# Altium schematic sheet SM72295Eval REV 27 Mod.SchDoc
size D; DrawnBy: *Dee Lim; Engineer: *Steve Brown; DocumentNumber: *TIDA-00558; PageSetup: Record=PageOptions¦CenterHorizontal=True¦CenterVertical=True¦PrintScale=0.51¦XCorrection=1.00¦YCorrection=1.00¦PrintKind=1¦BorderSize=5000000¦LeftOffset=0¦BottomOffset=0¦Orientation=2¦PaperLength=1000¦PaperWidth=1000¦Scale=100¦PaperSource=15¦PrintQuality=600¦MediaType=1¦DitherType=10¦PaperKind=Tabloid (11 x 17")¦PrintScaleMode=1
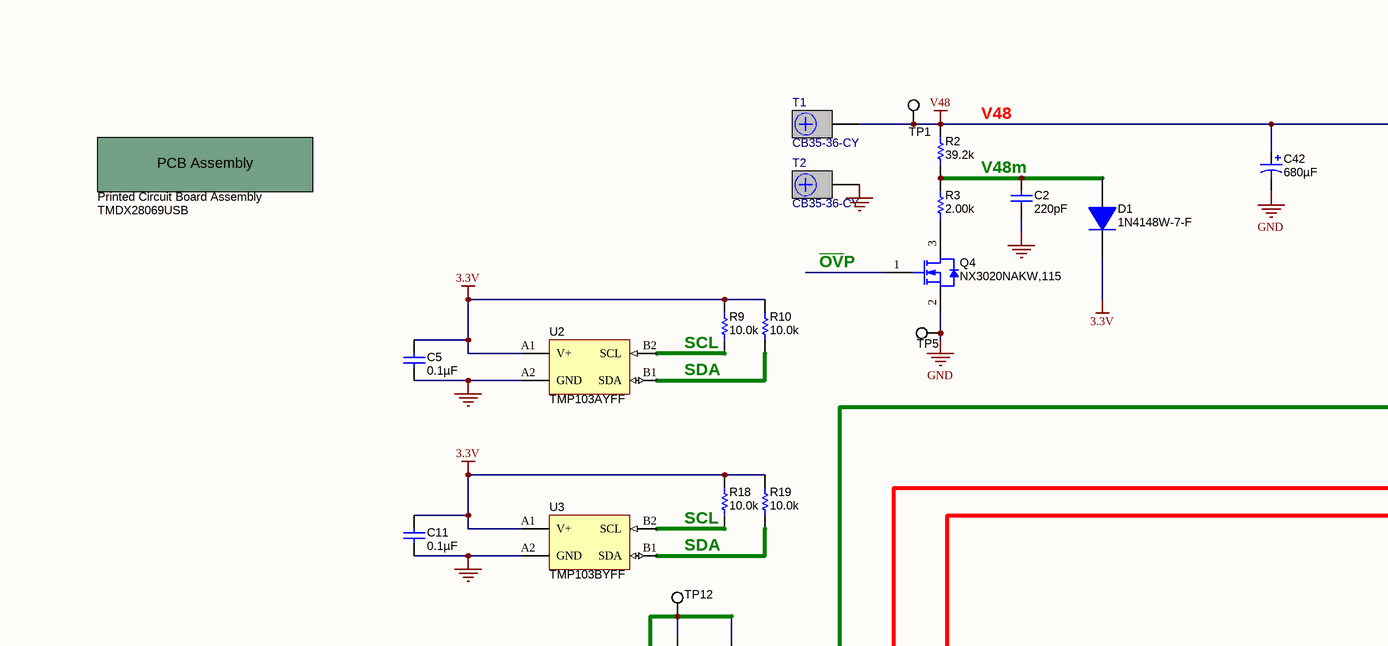
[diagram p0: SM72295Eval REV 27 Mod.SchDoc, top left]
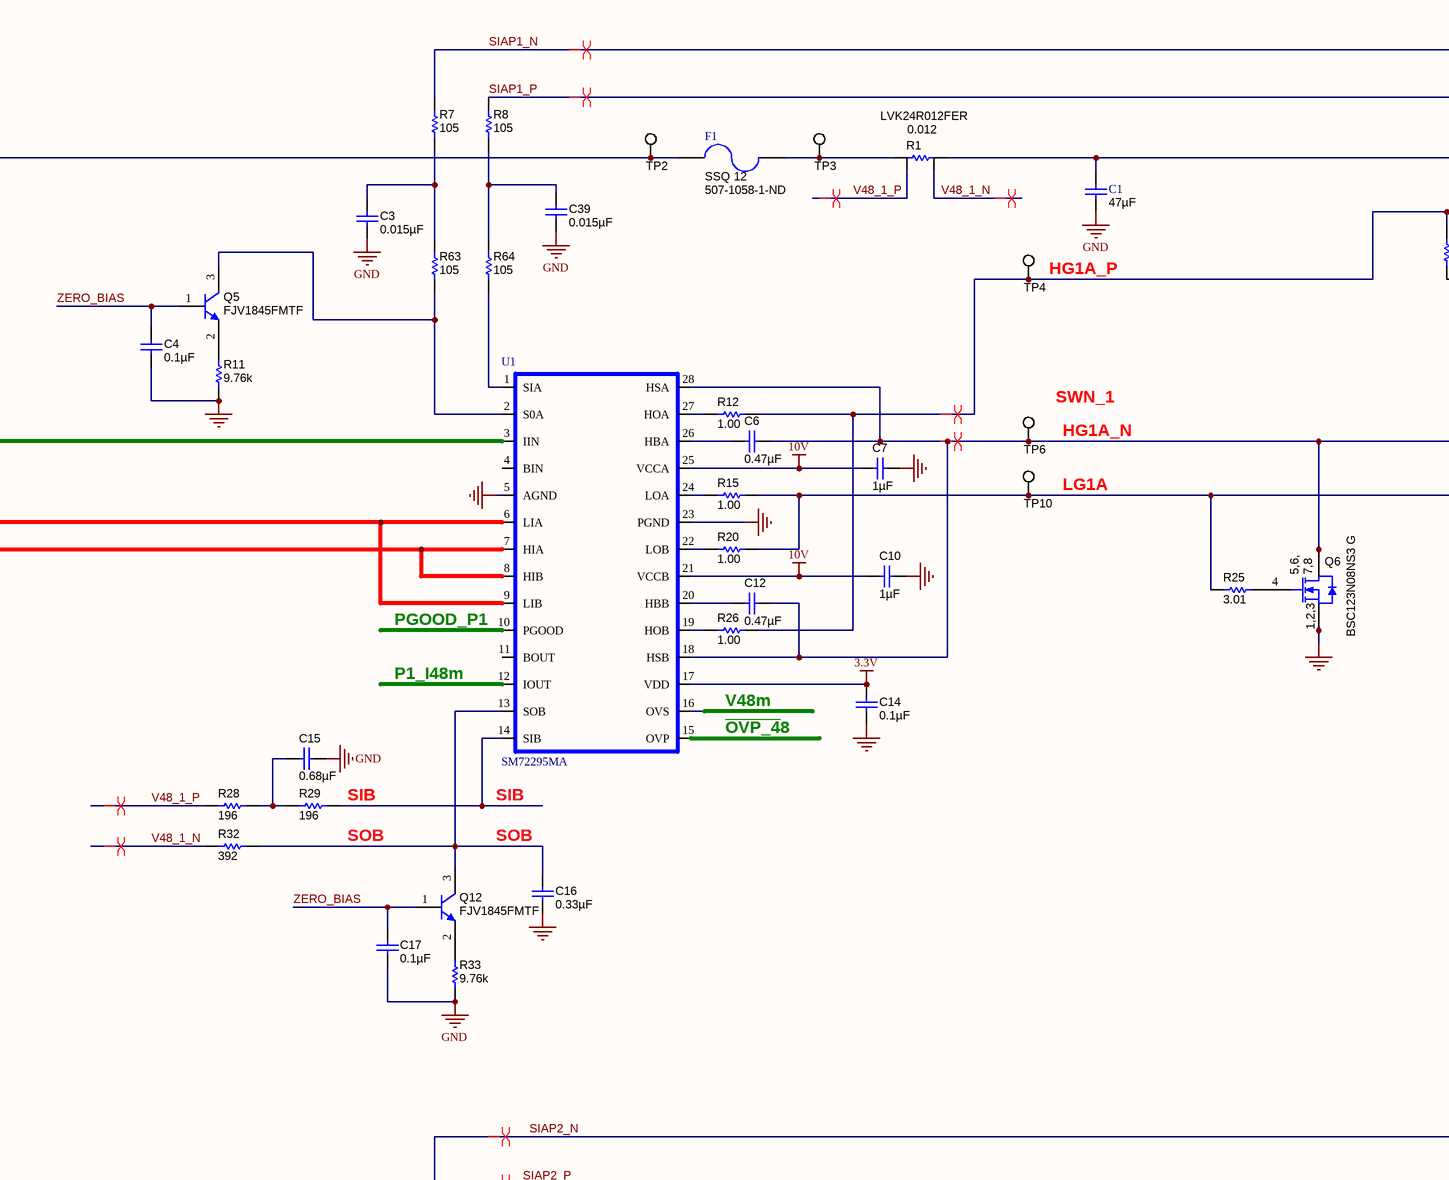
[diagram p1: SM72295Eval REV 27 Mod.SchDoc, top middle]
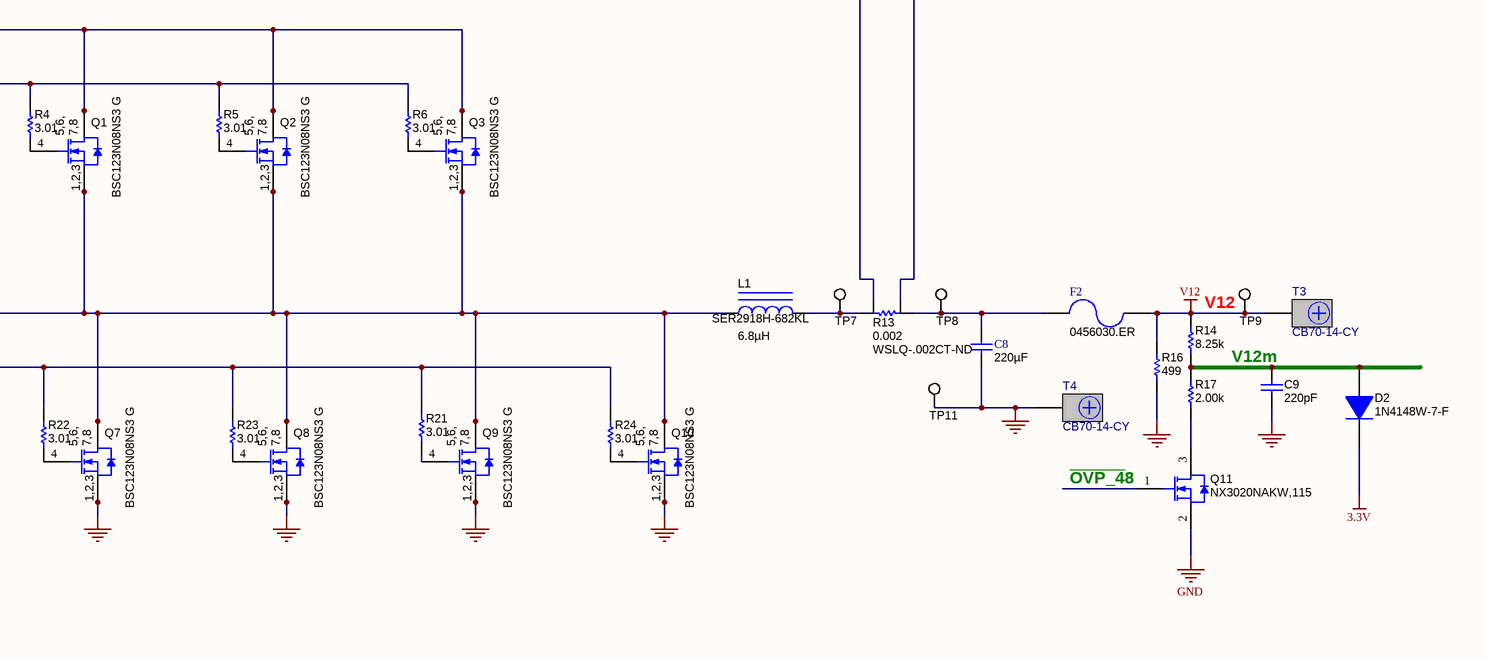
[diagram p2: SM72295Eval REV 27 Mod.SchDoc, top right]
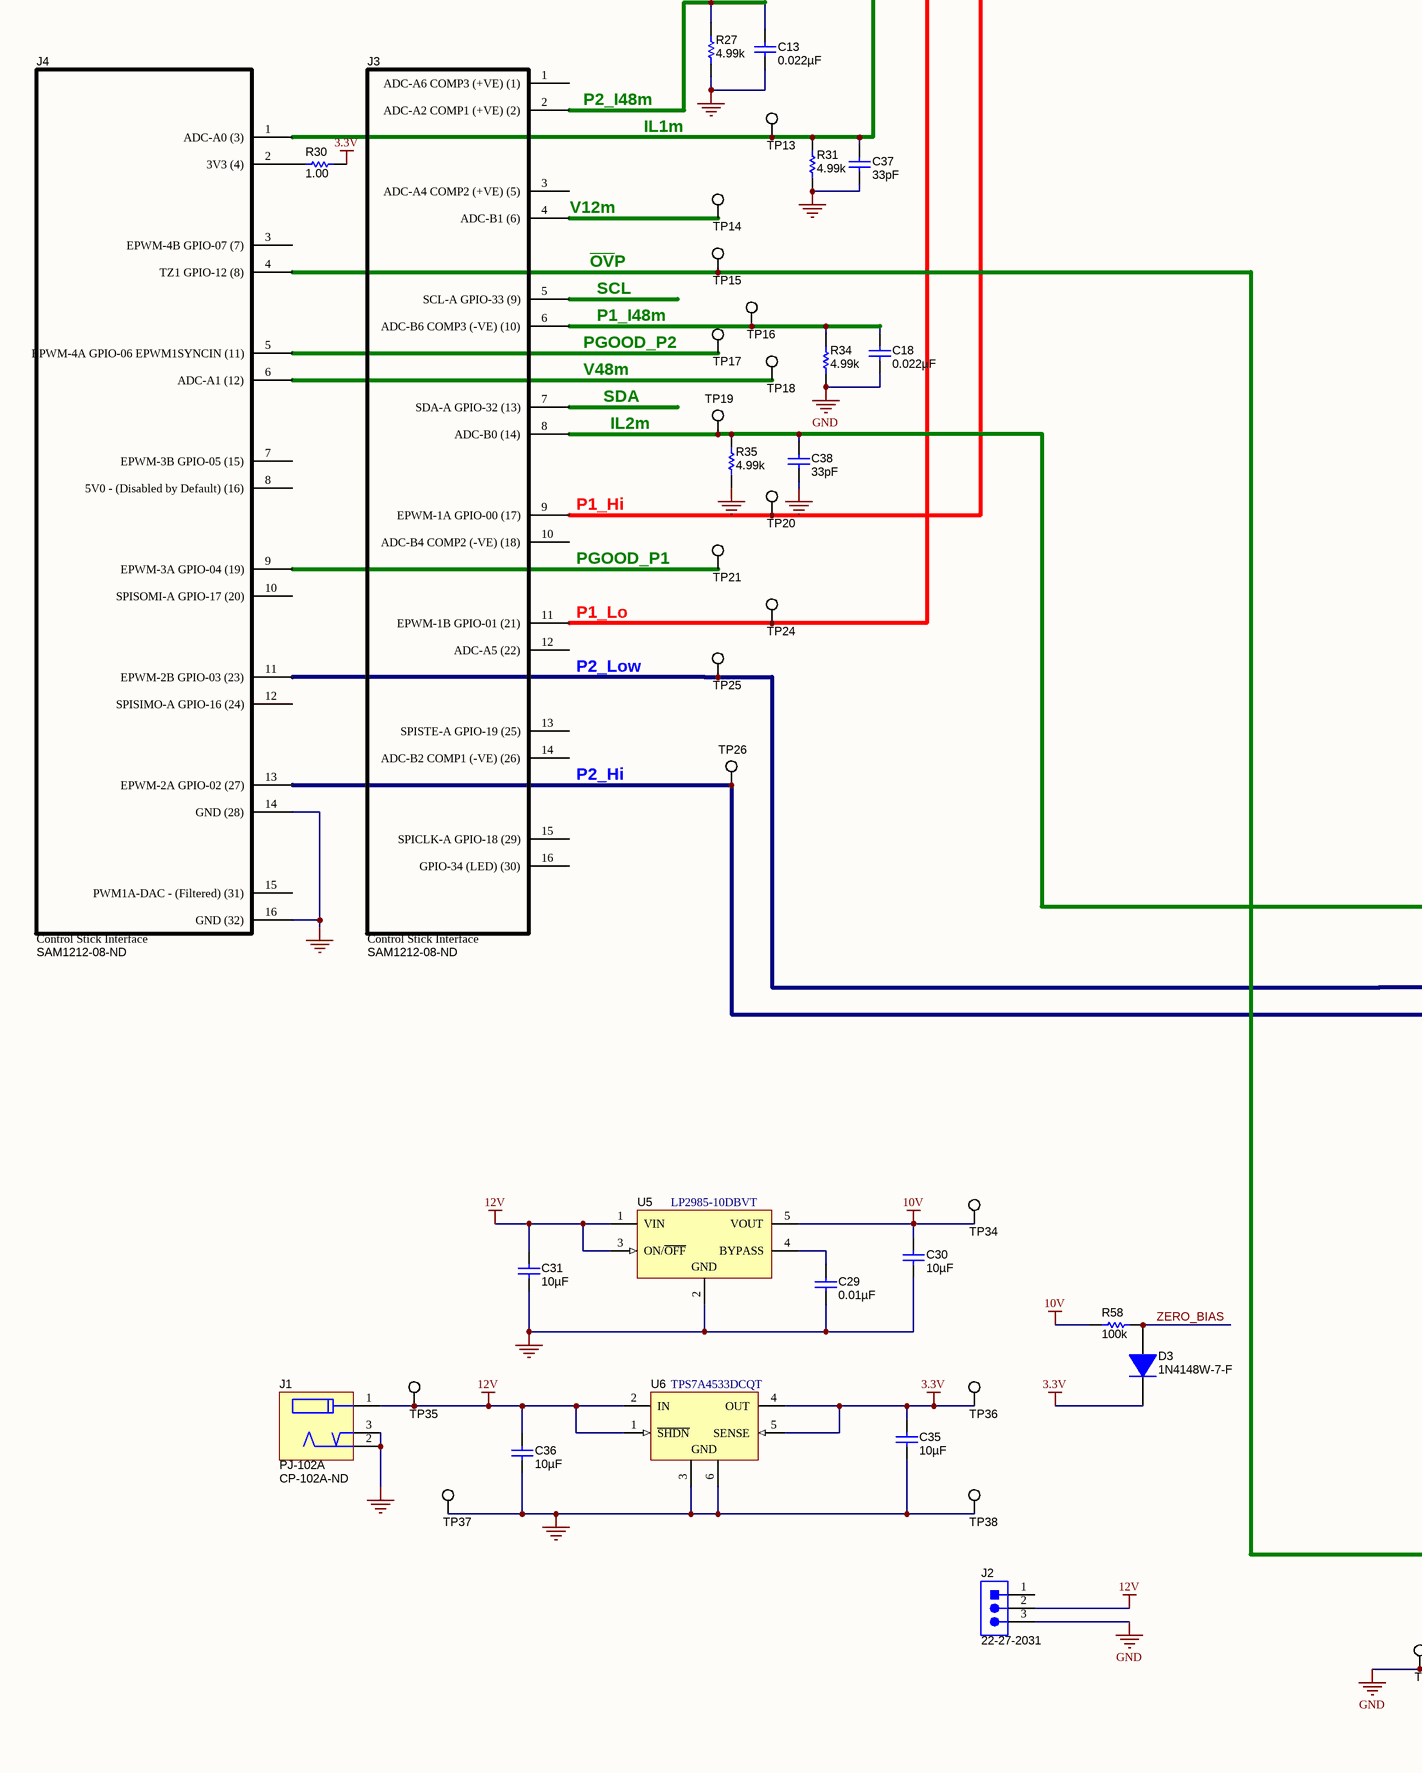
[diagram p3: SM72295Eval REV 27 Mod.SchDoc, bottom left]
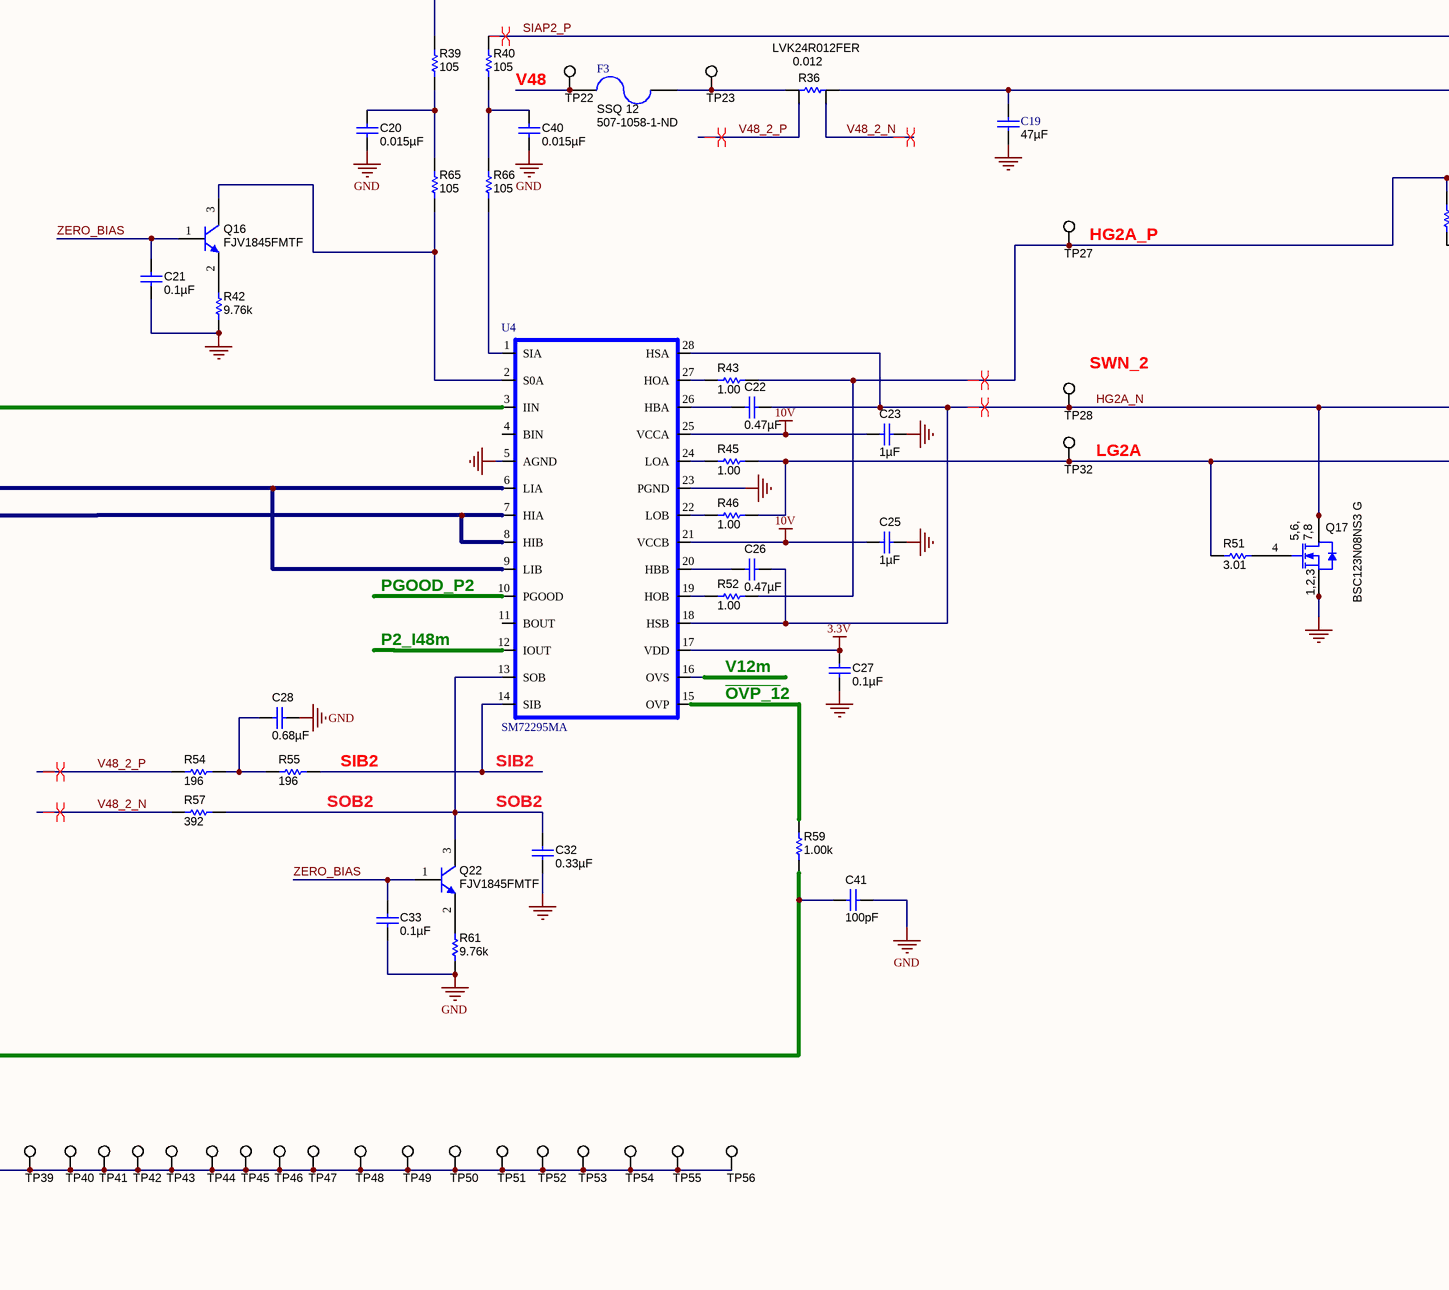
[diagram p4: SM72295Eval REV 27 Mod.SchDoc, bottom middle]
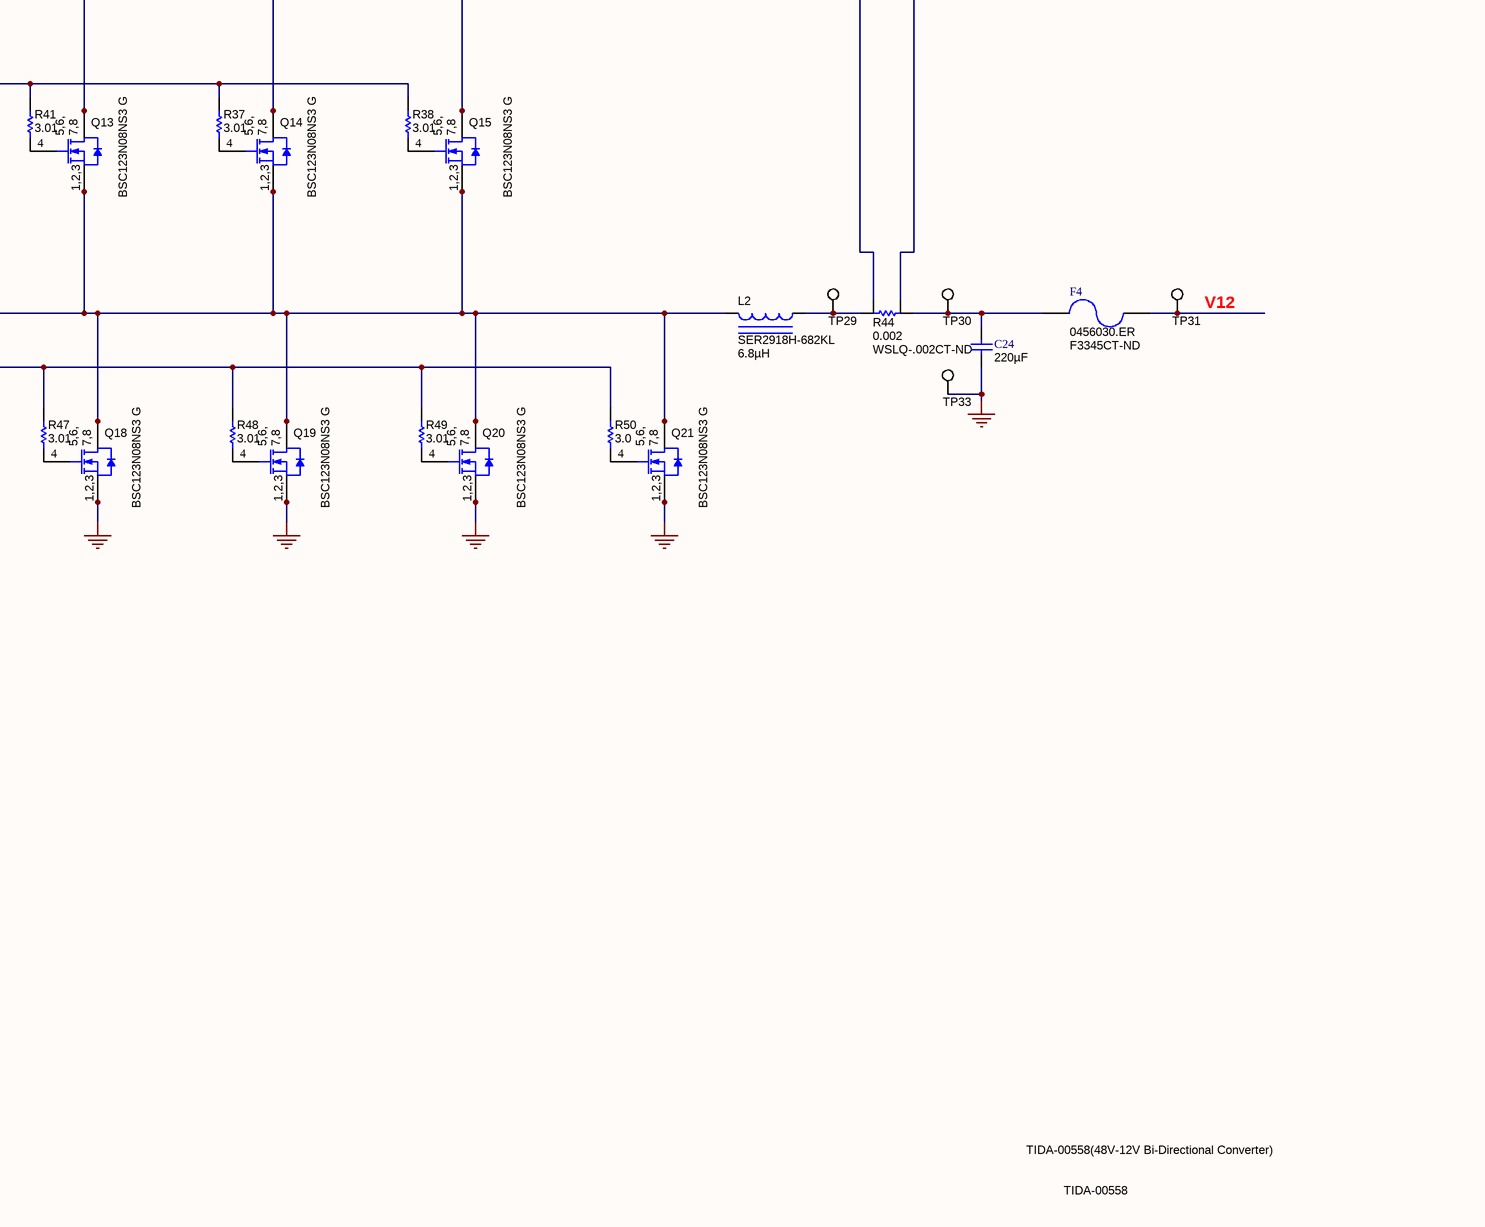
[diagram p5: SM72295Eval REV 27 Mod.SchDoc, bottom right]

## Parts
C1  ValueDisplayed: 47µF  [AVX-ST20-J10]  (hidden comment: RT201C476MAJ10)
C2  ValueDisplayed: 220pF  [0805_HV]  (hidden comment: C0805C221J1GACTU)
C3  ValueDisplayed: 0.015µF  [1206]  (hidden comment: 12061C153JAT2A)
C4  ValueDisplayed: 0.1µF  [0805_HV]  (hidden comment: 08055C104KAT2A)
C5  ValueDisplayed: 0.1µF  [0805_HV]  (hidden comment: 08053C104KAT2A)
C6  ValueDisplayed: 0.47µF  [0805_HV]  (hidden comment: C2012X7R1E474K)
C7  ValueDisplayed: 1µF  [0805_HV]  (hidden comment: C2012X7R1E105K)
C8  ValueDisplayed: 220µF  [AVX-ST20-J10]  (hidden comment: RT203C227MAJ10)
C9  ValueDisplayed: 220pF  [0805_HV]  (hidden comment: 08055A221JAT2A)
C10  ValueDisplayed: 1µF  [0805_HV]  (hidden comment: C2012X7R1E105K)
C11  ValueDisplayed: 0.1µF  [0805_HV]  (hidden comment: 08053C104KAT2A)
C12  ValueDisplayed: 0.47µF  [0805_HV]  (hidden comment: C2012X7R1E474K)
C13  ValueDisplayed: 0.022µF  [0805_HV]  (hidden comment: C0805C223K5RACTU)
C14  ValueDisplayed: 0.1µF  [0805_HV]  (hidden comment: 08053C104KAT2A)
C15  ValueDisplayed: 0.68µF  [1206_190]  (hidden comment: CGA5L2X7R2A684K160AA)
C16  ValueDisplayed: 0.33µF  [1206]  (hidden comment: C3216X7R2A334K130AA)
C17  ValueDisplayed: 0.1µF  [0805_HV]  (hidden comment: 08055C104KAT2A)
C18  ValueDisplayed: 0.022µF  [0805_HV]  (hidden comment: C0805C223K5RACTU)
C19  ValueDisplayed: 47µF  [AVX-ST20-J10]  (hidden comment: RT201C476MAJ10)
C20  ValueDisplayed: 0.015µF  [1206]  (hidden comment: 12061C153JAT2A)
C21  ValueDisplayed: 0.1µF  [0805_HV]  (hidden comment: 08055C104KAT2A)
C22  ValueDisplayed: 0.47µF  [0805_HV]  (hidden comment: C2012X7R1E474K)
C23  ValueDisplayed: 1µF  [0805_HV]  (hidden comment: C2012X7R1E105K)
C24  ValueDisplayed: 220µF  [AVX-ST20-J10]  (hidden comment: RT203C227MAJ10)
C25  ValueDisplayed: 1µF  [0805_HV]  (hidden comment: C2012X7R1E105K)
C26  ValueDisplayed: 0.47µF  [0805_HV]  (hidden comment: C2012X7R1E474K)
C27  ValueDisplayed: 0.1µF  [0805_HV]  (hidden comment: 08053C104KAT2A)
C28  ValueDisplayed: 0.68µF  [1206_190]  (hidden comment: CGA5L2X7R2A684K160AA)
C29  ValueDisplayed: 0.01µF  [0805_HV]  (hidden comment: 08055C103JAT2A)
C30  ValueDisplayed: 10µF  [1206]  (hidden comment: GRM31CR71E106KA12L)
C31  ValueDisplayed: 10µF  [1206]  (hidden comment: GRM31CR71E106KA12L)
C32  ValueDisplayed: 0.33µF  [1206]  (hidden comment: C3216X7R2A334K130AA)
C33  ValueDisplayed: 0.1µF  [0805_HV]  (hidden comment: 08055C104KAT2A)
C35  ValueDisplayed: 10µF  [0805_145]  (hidden comment: EMK212BB7106MG-T)
C36  ValueDisplayed: 10µF  [1206]  (hidden comment: GRM31CR71E106KA12L)
C37  ValueDisplayed: 33pF  [0805_HV]  (hidden comment: 08055A330JAT2A)
C38  ValueDisplayed: 33pF  [0805_HV]  (hidden comment: 08055A330JAT2A)
C39  ValueDisplayed: 0.015µF  [1206]  (hidden comment: 12061C153JAT2A)
C40  ValueDisplayed: 0.015µF  [1206]  (hidden comment: 12061C153JAT2A)
C41  ValueDisplayed: 100pF  [0805_HV]  (hidden comment: 08055A101JAT2A)
C42  ValueDisplayed: 680µF  [GPA_1800x3000]  (hidden comment: EGPA800ELL681MM30S)
D1  1N4148W-7-F  [SOD-123]
D2  1N4148W-7-F  [SOD-123]
D3  1N4148W-7-F  [SOD-123]
F1  SSQ 12  Supplier Part Number: 507-1058-1-ND  [SSQ]
F2  0456030.ER  [456]
F3  SSQ 12  Supplier Part Number: 507-1058-1-ND  [SSQ]
F4  0456030.ER  Supplier Part Number: F3345CT-ND  [456]
J1  PJ-102A  Supplier Part Number: CP-102A-ND  [PJ-102A]
J2  22-27-2031  [MOLEX_22-27-2031]
J3  Name: Control Stick Interface  Supplier Part Number: SAM1212-08-ND  [Samtec_SSW-108-01-x-D]  (hidden comment: TMDX28069USB_HALF ONE)
J4  Name: Control Stick Interface  Supplier Part Number: SAM1212-08-ND  [Samtec_SSW-108-01-x-D]  (hidden comment: TMDX28069USB_HALF TWO)
L1  SER2918H-682KL  ValueDisplayed: 6.8µH  [SER2918]
L2  SER2918H-682KL  ValueDisplayed: 6.8µH  [SER2918]
PCBA1  Printed Circuit Board Assembly  (mechanical)
Q1  BSC123N08NS3 G  [PG-TDSON-8 WITH VIAS]
Q2  BSC123N08NS3 G  [PG-TDSON-8 WITH VIAS]
Q3  BSC123N08NS3 G  [PG-TDSON-8 WITH VIAS]
Q4  NX3020NAKW,115  [SOT-323]
Q5  FJV1845FMTF  [SOT-23]
Q6  BSC123N08NS3 G  [PG-TDSON-8 WITH VIAS]
Q7  BSC123N08NS3 G  [PG-TDSON-8 WITH VIAS]
Q8  BSC123N08NS3 G  [PG-TDSON-8 WITH VIAS]
Q9  BSC123N08NS3 G  [PG-TDSON-8 WITH VIAS]
Q10  BSC123N08NS3 G  [PG-TDSON-8 WITH VIAS]
Q11  NX3020NAKW,115  [SOT-323]
Q12  FJV1845FMTF  [SOT-23]
Q13  BSC123N08NS3 G  [PG-TDSON-8 WITH VIAS]
Q14  BSC123N08NS3 G  [PG-TDSON-8 WITH VIAS]
Q15  BSC123N08NS3 G  [PG-TDSON-8 WITH VIAS]
Q16  FJV1845FMTF  [SOT-23]
Q17  BSC123N08NS3 G  [PG-TDSON-8 WITH VIAS]
Q18  BSC123N08NS3 G  [PG-TDSON-8 WITH VIAS]
Q19  BSC123N08NS3 G  [PG-TDSON-8 WITH VIAS]
Q20  BSC123N08NS3 G  [PG-TDSON-8 WITH VIAS]
Q21  BSC123N08NS3 G  [PG-TDSON-8 WITH VIAS]
Q22  FJV1845FMTF  [SOT-23]
R1  LVK24R012FER  ValueDisplayed: 0.012  [LVK24]
R2  ValueDisplayed: 39.2k  [0805_HV]  (hidden comment: CRCW080539K2FKEA)
R3  ValueDisplayed: 2.00k  [0805_HV]  (hidden comment: CRCW08052K00FKEA)
R4  ValueDisplayed: 3.01  [0805_HV]  (hidden comment: CRCW08053R01FKEA)
R5  ValueDisplayed: 3.01  [0805_HV]  (hidden comment: CRCW08053R01FKEA)
R6  ValueDisplayed: 3.01  [0805_HV]  (hidden comment: CRCW08053R01FKEA)
R7  ValueDisplayed: 105  [0805_HV]  (hidden comment: CRCW0805105RFKEA)
R8  ValueDisplayed: 105  [0805_HV]  (hidden comment: CRCW0805105RFKEA)
R9  ValueDisplayed: 10.0k  [0805_HV]  (hidden comment: CRCW080510K0FKEA)
R10  ValueDisplayed: 10.0k  [0805_HV]  (hidden comment: CRCW080510K0FKEA)
R11  ValueDisplayed: 9.76k  [0805_HV]  (hidden comment: CRCW08059K76FKEA)
R12  ValueDisplayed: 1.00  [0805_HV]  (hidden comment: CRCW08051R00FKEA)
R13  ValueDisplayed: 0.002  Supplier Part Number: WSLQ-.002CT-ND  [RES_WSL2726 WITH VIAS]  (hidden comment: WSL27262L000FEB)
R14  ValueDisplayed: 8.25k  [0805_HV]  (hidden comment: CRCW08058K25FKEA)
R15  ValueDisplayed: 1.00  [0805_HV]  (hidden comment: CRCW08051R00FKEA)
R16  ValueDisplayed: 499  [1206]  (hidden comment: CRCW1206499RFKEA)
R17  ValueDisplayed: 2.00k  [0805_HV]  (hidden comment: CRCW08052K00FKEA)
R18  ValueDisplayed: 10.0k  [0805_HV]  (hidden comment: CRCW080510K0FKEA)
R19  ValueDisplayed: 10.0k  [0805_HV]  (hidden comment: CRCW080510K0FKEA)
R20  ValueDisplayed: 1.00  [0805_HV]  (hidden comment: CRCW08051R00FKEA)
R21  ValueDisplayed: 3.01  [0805_HV]  (hidden comment: CRCW08053R01FKEA)
R22  ValueDisplayed: 3.01  [0805_HV]  (hidden comment: CRCW08053R01FKEA)
R23  ValueDisplayed: 3.01  [0805_HV]  (hidden comment: CRCW08053R01FKEA)
R24  ValueDisplayed: 3.01  [0805_HV]  (hidden comment: CRCW08053R01FKEA)
R25  ValueDisplayed: 3.01  [0805_HV]  (hidden comment: CRCW08053R01FKEA)
R26  ValueDisplayed: 1.00  [0805_HV]  (hidden comment: CRCW08051R00FKEA)
R27  ValueDisplayed: 4.99k  [0805_HV]  (hidden comment: CRCW08054K99FKEA)
R28  ValueDisplayed: 196  [0805_HV]  (hidden comment: CRCW0805196RFKEA)
R29  ValueDisplayed: 196  [0805_HV]  (hidden comment: CRCW0805196RFKEA)
R30  ValueDisplayed: 1.00  [0805_HV]  (hidden comment: CRCW08051R00FKEA)
R31  ValueDisplayed: 4.99k  [0805_HV]  (hidden comment: CRCW08054K99FKEA)
R32  ValueDisplayed: 392  [0805_HV]  (hidden comment: CRCW0805392RFKEA)
R33  ValueDisplayed: 9.76k  [0805_HV]  (hidden comment: CRCW08059K76FKEA)
R34  ValueDisplayed: 4.99k  [0805_HV]  (hidden comment: CRCW08054K99FKEA)
R35  ValueDisplayed: 4.99k  [0805_HV]  (hidden comment: CRCW08054K99FKEA)
R36  LVK24R012FER  ValueDisplayed: 0.012  [LVK24]
R37  ValueDisplayed: 3.01  [0805_HV]  (hidden comment: CRCW08053R01FKEA)
R38  ValueDisplayed: 3.01  [0805_HV]  (hidden comment: CRCW08053R01FKEA)
R39  ValueDisplayed: 105  [0805_HV]  (hidden comment: CRCW0805105RFKEA)
R40  ValueDisplayed: 105  [0805_HV]  (hidden comment: CRCW0805105RFKEA)
R41  ValueDisplayed: 3.01  [0805_HV]  (hidden comment: CRCW08053R01FKEA)
R42  ValueDisplayed: 9.76k  [0805_HV]  (hidden comment: CRCW08059K76FKEA)
R43  ValueDisplayed: 1.00  [0805_HV]  (hidden comment: CRCW08051R00FKEA)
R44  ValueDisplayed: 0.002  Supplier Part Number: WSLQ-.002CT-ND  [RES_WSL2726 WITH VIAS]  (hidden comment: WSL27262L000FEB)
R45  ValueDisplayed: 1.00  [0805_HV]  (hidden comment: CRCW08051R00FKEA)
R46  ValueDisplayed: 1.00  [0805_HV]  (hidden comment: CRCW08051R00FKEA)
R47  ValueDisplayed: 3.01  [0805_HV]  (hidden comment: CRCW08053R01FKEA)
R48  ValueDisplayed: 3.01  [0805_HV]  (hidden comment: CRCW08053R01FKEA)
R49  ValueDisplayed: 3.01  [0805_HV]  (hidden comment: CRCW08053R01FKEA)
R50  ValueDisplayed: 3.0  [0805_HV]  (hidden comment: CRCW08053R00JNEA)
R51  ValueDisplayed: 3.01  [0805_HV]  (hidden comment: CRCW08053R01FKEA)
R52  ValueDisplayed: 1.00  [0805_HV]  (hidden comment: CRCW08051R00FKEA)
R54  ValueDisplayed: 196  [0805_HV]  (hidden comment: CRCW0805196RFKEA)
R55  ValueDisplayed: 196  [0805_HV]  (hidden comment: CRCW0805196RFKEA)
R57  ValueDisplayed: 392  [0805_HV]  (hidden comment: CRCW0805392RFKEA)
R58  ValueDisplayed: 100k  [0805_HV]  (hidden comment: CRCW0805100KFKEA)
R59  ValueDisplayed: 1.00k  [0805_HV]  (hidden comment: CRCW08051K00FKEA)
R61  ValueDisplayed: 9.76k  [0805_HV]  (hidden comment: CRCW08059K76FKEA)
R63  ValueDisplayed: 105  [0805_HV]  (hidden comment: CRCW0805105RFKEA)
R64  ValueDisplayed: 105  [0805_HV]  (hidden comment: CRCW0805105RFKEA)
R65  ValueDisplayed: 105  [0805_HV]  (hidden comment: CRCW0805105RFKEA)
R66  ValueDisplayed: 105  [0805_HV]  (hidden comment: CRCW0805105RFKEA)
T1  CB35-36-CY  [CB35-36-CY]
T2  CB35-36-CY  [CB35-36-CY]
T3  CB70-14-CY  [CB70-14-CY]
T4  CB70-14-CY  [CB70-14-CY]
TP1  5015  [Testpoint_Keystone_Miniature]  (value not drawn)
TP2  5015  [Testpoint_Keystone_Miniature]  (value not drawn)
TP3  5015  [Testpoint_Keystone_Miniature]  (value not drawn)
TP4  5015  [Testpoint_Keystone_Miniature]  (value not drawn)
TP5  5015  [Testpoint_Keystone_Miniature]  (value not drawn)
TP6  5015  [Testpoint_Keystone_Miniature]  (value not drawn)
TP7  5015  [Testpoint_Keystone_Miniature]  (value not drawn)
TP8  5015  [Testpoint_Keystone_Miniature]  (value not drawn)
TP9  5015  [Testpoint_Keystone_Miniature]  (value not drawn)
TP10  5015  [Testpoint_Keystone_Miniature]  (value not drawn)
TP11  5015  [Testpoint_Keystone_Miniature]  (value not drawn)
TP12  5015  [Testpoint_Keystone_Miniature]  (value not drawn)
TP13  5015  [Testpoint_Keystone_Miniature]  (value not drawn)
TP14  5015  [Testpoint_Keystone_Miniature]  (value not drawn)
TP15  5015  [Testpoint_Keystone_Miniature]  (value not drawn)
TP16  5015  [Testpoint_Keystone_Miniature]  (value not drawn)
TP17  5015  [Testpoint_Keystone_Miniature]  (value not drawn)
TP18  5015  [Testpoint_Keystone_Miniature]  (value not drawn)
TP19  5015  [Testpoint_Keystone_Miniature]  (value not drawn)
TP20  5015  [Testpoint_Keystone_Miniature]  (value not drawn)
TP21  5015  [Testpoint_Keystone_Miniature]  (value not drawn)
TP22  5015  [Testpoint_Keystone_Miniature]  (value not drawn)
TP23  5015  [Testpoint_Keystone_Miniature]  (value not drawn)
TP24  5015  [Testpoint_Keystone_Miniature]  (value not drawn)
TP25  5015  [Testpoint_Keystone_Miniature]  (value not drawn)
TP26  5015  [Testpoint_Keystone_Miniature]  (value not drawn)
TP27  5015  [Testpoint_Keystone_Miniature]  (value not drawn)
TP28  5015  [Testpoint_Keystone_Miniature]  (value not drawn)
TP29  5015  [Testpoint_Keystone_Miniature]  (value not drawn)
TP30  5015  [Testpoint_Keystone_Miniature]  (value not drawn)
TP31  5015  [Testpoint_Keystone_Miniature]  (value not drawn)
TP32  5015  [Testpoint_Keystone_Miniature]  (value not drawn)
TP33  5015  [Testpoint_Keystone_Miniature]  (value not drawn)
TP34  5015  [Testpoint_Keystone_Miniature]  (value not drawn)
TP35  5015  [Testpoint_Keystone_Miniature]  (value not drawn)
TP36  5015  [Testpoint_Keystone_Miniature]  (value not drawn)
TP37  5015  [Testpoint_Keystone_Miniature]  (value not drawn)
TP38  5015  [Testpoint_Keystone_Miniature]  (value not drawn)
TP39  5015  [Testpoint_Keystone_Miniature]  (value not drawn)
TP40  5015  [Testpoint_Keystone_Miniature]  (value not drawn)
TP41  5015  [Testpoint_Keystone_Miniature]  (value not drawn)
TP42  5015  [Testpoint_Keystone_Miniature]  (value not drawn)
TP43  5015  [Testpoint_Keystone_Miniature]  (value not drawn)
TP44  5015  [Testpoint_Keystone_Miniature]  (value not drawn)
TP45  5015  [Testpoint_Keystone_Miniature]  (value not drawn)
TP46  5015  [Testpoint_Keystone_Miniature]  (value not drawn)
TP47  5015  [Testpoint_Keystone_Miniature]  (value not drawn)
TP48  5015  [Testpoint_Keystone_Miniature]  (value not drawn)
TP49  5015  [Testpoint_Keystone_Miniature]  (value not drawn)
TP50  5015  [Testpoint_Keystone_Miniature]  (value not drawn)
TP51  5015  [Testpoint_Keystone_Miniature]  (value not drawn)
TP52  5015  [Testpoint_Keystone_Miniature]  (value not drawn)
TP53  5015  [Testpoint_Keystone_Miniature]  (value not drawn)
TP54  5015  [Testpoint_Keystone_Miniature]  (value not drawn)
TP55  5015  [Testpoint_Keystone_Miniature]  (value not drawn)
TP56  5015  [Testpoint_Keystone_Miniature]  (value not drawn)
U1  SM72295MA  [SO28_DW]
U2  TMP103AYFF  [YFF0004AAAA]
U3  TMP103BYFF  [YFF0004AAAA]
U4  SM72295MA  [SO28_DW]
U5  LP2985-10DBVT  [DBV0005A_N]
U6  TPS7A4533DCQT  [DCQ0006A_N]

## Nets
3.3V: C5.1 C11.1 C14.1 C27.1 C35.1 D1.1(K) D2.1(K) D3.1(K) R9.1 R10.1 R18.1 R19.1 R30.2 TP36.1 U1.17(VDD) U2.A1(V+) U3.A1(V+) U4.17(VDD) U6.4(OUT) U6.5(SENSE)
10V: C7.1 C10.1 C23.1 C25.1 C30.1 R58.1 TP34.1 U1.21(VCCB) U1.25(VCCA) U4.21(VCCB) U4.25(VCCA) U5.5(VOUT)
12V: C31.1 C36.1 J1.1 J2.2 TP35.1 U5.1(VIN) U5.3(ON/~{OFF}) U6.1(~{SHDN}) U6.2(IN)
GND: C1.1 C2.2 C3.1 C4.2 C5.2 C7.2 C8.1 C9.2 C10.2 C11.2 C13.2 C14.2 C15.2 C16.2 C17.2 C18.2 C19.1 C20.1 C21.2 C23.2 C24.1 C25.2 C27.2 C28.2 C29.2 C30.2 C31.2 C32.2 C33.2 C35.2 C36.2 C37.2 C38.2 C39.1 C40.1 C41.1 C42.2(-) J1.2 J1.3 J2.3 J4.14(GND_(28)) J4.16(GND_(32)) Q4.2(S) Q6.1(S) Q6.2(S) Q6.3(S) Q7.1(S) Q7.2(S) Q7.3(S) Q8.1(S) Q8.2(S) Q8.3(S) Q9.1(S) Q9.2(S) Q9.3(S) Q10.1(S) Q10.2(S) Q10.3(S) Q11.2(S) Q17.1(S) Q17.2(S) Q17.3(S) Q18.1(S) Q18.2(S) Q18.3(S) Q19.1(S) Q19.2(S) Q19.3(S) Q20.1(S) Q20.2(S) Q20.3(S) Q21.1(S) Q21.2(S) Q21.3(S) R11.1 R16.1 R27.1 R31.1 R33.1 R34.1 R35.1 R42.1 R61.1 T2.1 T4.1 TP5.1 TP11.1 TP33.1 TP37.1 TP38.1 TP39.1 TP40.1 TP41.1 TP42.1 TP43.1 TP44.1 TP45.1 TP46.1 TP47.1 TP48.1 TP49.1 TP50.1 TP51.1 TP52.1 TP53.1 TP54.1 TP55.1 TP56.1 U1.5(AGND) U1.23(PGND) U2.A2(GND) U3.A2(GND) U4.5(AGND) U4.23(PGND) U5.2(GND) U6.3(GND) U6.6(GND)
V12: F2.1 F4.1 R14.2 R16.2 T3.1 TP9.1 TP31.1
V48: C42.1(+) F1.2 F3.2 R2.2 T1.1 TP1.1 TP2.1 TP22.1
~{OV}P: C41.2 J4.4(TZ1_GPIO-12_(8)) Q4.1(G) R59.1 TP15.1
~{OVP_1}2: R59.2 U4.15(OVP)
~{OVP_4}8: Q11.1(G) U1.15(OVP)
HG1A_N: C6.1 C12.1 L1.1 Q1.1(S) Q1.2(S) Q1.3(S) Q2.1(S) Q2.2(S) Q2.3(S) Q3.1(S) Q3.2(S) Q3.3(S) Q6.5(D) Q6.6(D) Q6.7(D) Q6.8(D) Q6.9(D) Q7.5(D) Q7.6(D) Q7.7(D) Q7.8(D) Q7.9(D) Q8.5(D) Q8.6(D) Q8.7(D) Q8.8(D) Q8.9(D) Q9.5(D) Q9.6(D) Q9.7(D) Q9.8(D) Q9.9(D) Q10.5(D) Q10.6(D) Q10.7(D) Q10.8(D) Q10.9(D) TP6.1 U1.18(HSB) U1.28(HSA)
HG1A_P: R4.1 R5.2 R6.2 R12.2 R26.2 TP4.1
HG2A_N: C22.1 C26.1 L2.2 Q13.1(S) Q13.2(S) Q13.3(S) Q14.1(S) Q14.2(S) Q14.3(S) Q15.1(S) Q15.2(S) Q15.3(S) Q17.5(D) Q17.6(D) Q17.7(D) Q17.8(D) Q17.9(D) Q18.5(D) Q18.6(D) Q18.7(D) Q18.8(D) Q18.9(D) Q19.5(D) Q19.6(D) Q19.7(D) Q19.8(D) Q19.9(D) Q20.5(D) Q20.6(D) Q20.7(D) Q20.8(D) Q20.9(D) Q21.5(D) Q21.6(D) Q21.7(D) Q21.8(D) Q21.9(D) TP28.1 U4.18(HSB) U4.28(HSA)
HG2A_P: R37.2 R38.2 R41.1 R43.2 R52.2 TP27.1
IL1m: C37.1 J4.1(ADC-A0_(3)) R31.2 TP13.1 U1.3(IIN)
IL2m: C38.1 J3.8(ADC-B0_(14)) R35.2 TP19.1 U4.3(IIN)
LG1A: R15.2 R20.2 R21.2 R22.2 R23.2 R24.2 R25.1 TP10.1
LG2A: R45.2 R46.2 R47.2 R48.2 R49.2 R50.2 R51.2 TP32.1
P1_Hi: J3.9(EPWM-1A_GPIO-00_(17)) TP20.1 U1.7(HIA) U1.8(HIB)
P1_I48m: C18.1 J3.6(ADC-B6_COMP3_(-VE)_(10)) R34.2 TP16.1 U1.12(IOUT)
P1_Lo: J3.11(EPWM-1B_GPIO-01_(21)) TP24.1 U1.6(LIA) U1.9(LIB)
P2_Hi: J4.13(EPWM-2A_GPIO-02_(27)) TP26.1 U4.7(HIA) U4.8(HIB)
P2_I48m: C13.1 J3.2(ADC-A2_COMP1_(+VE)_(2)) R27.2 TP12.1 U4.12(IOUT)
P2_Low: J4.11(EPWM-2B_GPIO-03_(23)) TP25.1 U4.6(LIA) U4.9(LIB)
PGOOD_P1: J4.9(EPWM-3A_GPIO-04_(19)) TP21.1 U1.10(PGOOD)
PGOOD_P2: J4.5(EPWM-4A_GPIO-06_EPWM1SYNCIN_(11)) TP17.1 U4.10(PGOOD)
SCL: J3.5(SCL-A_GPIO-33_(9)) R9.2 R18.2 U2.B2(SCL) U3.B2(SCL)
SDA: J3.7(SDA-A_GPIO-32_(13)) R10.2 R19.2 U2.B1(SDA) U3.B1(SDA)
SIAP1_N: R7.2 R13.3
SIAP1_P: R8.2 R13.4
SIAP2_N: R39.2 R44.4
SIAP2_P: R40.2 R44.3
SIB: R29.1 U1.14(SIB)
SIB2: R55.1 U4.14(SIB)
SOB: C16.1 Q12.3(C) R32.1 U1.13(SOB)
SOB2: C32.1 Q22.3(C) R57.1 U4.13(SOB)
V12m: C9.1 D2.2(A) J3.4(ADC-B1_(6)) R14.1 R17.2 TP14.1 U4.16(OVS)
V48_1_N: R1.3 R32.2
V48_1_P: R1.4 R28.2
V48_2_N: R36.3 R57.2
V48_2_P: R36.4 R54.2
V48m: C2.1 D1.2(A) J4.6(ADC-A1_(12)) R2.1 R3.2 TP18.1 U1.16(OVS)
ZERO_BIAS: C4.1 C17.1 C21.1 C33.1 D3.2(A) Q5.1(B) Q12.1(B) Q16.1(B) Q22.1(B) R58.2
NetC1_2: C1.2 Q1.5(D) Q1.6(D) Q1.7(D) Q1.8(D) Q1.9(D) Q2.5(D) Q2.6(D) Q2.7(D) Q2.8(D) Q2.9(D) Q3.5(D) Q3.6(D) Q3.7(D) Q3.8(D) Q3.9(D) R1.1
NetC3_2: C3.2 R7.1 R63.2
NetC6_2: C6.2 U1.26(HBA)
NetC8_2: C8.2 F2.2 R13.1 TP8.1
NetC12_2: C12.2 U1.20(HBB)
NetC15_1: C15.1 R28.1 R29.2
NetC19_2: C19.2 Q13.5(D) Q13.6(D) Q13.7(D) Q13.8(D) Q13.9(D) Q14.5(D) Q14.6(D) Q14.7(D) Q14.8(D) Q14.9(D) Q15.5(D) Q15.6(D) Q15.7(D) Q15.8(D) Q15.9(D) R36.1
NetC20_2: C20.2 R39.1 R65.2
NetC22_2: C22.2 U4.26(HBA)
NetC24_2: C24.2 F4.2 R44.2 TP30.1
NetC26_2: C26.2 U4.20(HBB)
NetC28_1: C28.1 R54.1 R55.2
NetC29_1: C29.1 U5.4(BYPASS)
NetC39_2: C39.2 R8.1 R64.2
NetC40_2: C40.2 R40.1 R66.2
NetF1_1: F1.1 R1.2 TP3.1
NetF3_1: F3.1 R36.2 TP23.1
NetJ4_2: J4.2(3V3_(4)) R30.1
NetL1_2: L1.2 R13.2 TP7.1
NetL2_1: L2.1 R44.1 TP29.1
NetQ1_4: Q1.4(G) R4.2
NetQ2_4: Q2.4(G) R5.1
NetQ3_4: Q3.4(G) R6.1
NetQ4_3: Q4.3(D) R3.1
NetQ5_2: Q5.2(E) R11.2
NetQ5_3: Q5.3(C) R63.1 U1.2(S0A)
NetQ6_4: Q6.4(G) R25.2
NetQ7_4: Q7.4(G) R22.1
NetQ8_4: Q8.4(G) R23.1
NetQ9_4: Q9.4(G) R21.1
NetQ10_4: Q10.4(G) R24.1
NetQ11_3: Q11.3(D) R17.1
NetQ12_2: Q12.2(E) R33.2
NetQ13_4: Q13.4(G) R41.2
NetQ14_4: Q14.4(G) R37.1
NetQ15_4: Q15.4(G) R38.1
NetQ16_2: Q16.2(E) R42.2
NetQ16_3: Q16.3(C) R65.1 U4.2(S0A)
NetQ17_4: Q17.4(G) R51.1
NetQ18_4: Q18.4(G) R47.1
NetQ19_4: Q19.4(G) R48.1
NetQ20_4: Q20.4(G) R49.1
NetQ21_4: Q21.4(G) R50.1
NetQ22_2: Q22.2(E) R61.2
NetR12_1: R12.1 U1.27(HOA)
NetR15_1: R15.1 U1.24(LOA)
NetR20_1: R20.1 U1.22(LOB)
NetR26_1: R26.1 U1.19(HOB)
NetR43_1: R43.1 U4.27(HOA)
NetR45_1: R45.1 U4.24(LOA)
NetR46_1: R46.1 U4.22(LOB)
NetR52_1: R52.1 U4.19(HOB)
NetR64_1: R64.1 U1.1(SIA)
NetR66_1: R66.1 U4.1(SIA)

Not connected (* = marked no-connect by the designer): J2 1; J3 1(ADC-A6_COMP3_(+VE)_(1)) 3(ADC-A4_COMP2_(+VE)_(5)) 10(ADC-B4_COMP2_(-VE)_(18)) 12(ADC-A5_(22)) 13(SPISTE-A_GPIO-19_(25)) 14(ADC-B2_COMP1_(-VE)_(26)) 15(SPICLK-A_GPIO-18_(29)) 16(GPIO-34_(LED)_(30)); J4 3(EPWM-4B_GPIO-07_(7)) 7(EPWM-3B_GPIO-05_(15)) 8(5V0_-_(Disabled_by_Default)_(16)) 10(SPISOMI-A_GPIO-17_(20)) 12(SPISIMO-A_GPIO-16_(24)) 15(PWM1A-DAC_-_(Filtered)_(31)); U1 4(BIN) 11(BOUT); U4 4(BIN) 11(BOUT)

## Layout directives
differential pair: HG1A_N, HG1A_P, HG2A_N, HG2A_P, SIAP1_N, SIAP1_P, SIAP2_N, SIAP2_P, V48_1_N, V48_1_P, V48_2_N, V48_2_P

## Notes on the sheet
- TIDA-00558(48V-12V Bi-Directional Converter)
- TIDA-00558
- Labels drawn without touching a wire or pin: SWN_1, SWN_2

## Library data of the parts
C1 C19 = RT201C476MAJ10: CAP, CERM, 47 µF, 100 V, +/- 20%, X7R, 1075x300mil; Manufacturer: AVX; Value: 47uF; Tolerance_%: 20; VDC_V: 100; Polarized: N; CompType: Capacitor; U/M: EA; Cap_F: 0.000047; Value1: Unknown; Value2: 100V; TaMin_C: -55; TaMax_C: 125; Cap_Case: 27.3x7.62mm
C2 = C0805C221J1GACTU: CAP, CERM, 220 pF, 100 V, +/- 5%, C0G/NP0, 0805; Manufacturer: Kemet; Polarized: N; CompType: Capacitor; Value: 220pF; U/M: EA; Cap_F: 0.00000000022; Tolerance_%: 5; ESR_ohm: 0.046; Value1: 0.046 ohm; VDC_V: 100; Value2: 100V; IRMS_A: 0.888; TaMin_C: -55; TaMax_C: 125; Cap_Case: 0805
C3 C20 C39 C40 = 12061C153JAT2A: CAP, CERM, 0.015 µF, 100 V, +/- 5%, X7R, 1206; Manufacturer: AVX; Polarized: N; CompType: Capacitor; Value: 0.015uF; U/M: EA; Cap_F: 0.000000015; Tolerance_%: 5; ESR_ohm: 0.096; Value1: 0.096 ohm; VDC_V: 100; Value2: 100V; TaMin_C: -55; TaMax_C: 125
C4 C17 C21 C33 = 08055C104KAT2A: CAP, CERM, 0.1 µF, 50 V, +/- 10%, X7R, 0805; Manufacturer: AVX; Polarized: N; CompType: Capacitor; Value: 0.1uF; U/M: EA; Cap_F: 0.0000001; Tolerance_%: 10; ESR_ohm: 0.024; Value1: 0.024 ohm; VDC_V: 50; Value2: 50V; TaMin_C: -55; TaMax_C: 125; Cap_Case: 0805
C5 C11 C14 C27 = 08053C104KAT2A: CAP, CERM, 0.1 µF, 25 V, +/- 10%, X7R, 0805; Manufacturer: AVX; Polarized: N; CompType: Capacitor; Value: 0.1uF; U/M: EA; Cap_F: 0.0000001; Tolerance_%: 10; ESR_ohm: 0.28; Value1: 0.28 ohm; VDC_V: 25; Value2: 25V; TaMin_C: -55; TaMax_C: 125; Cap_Case: 0805
C6 C12 C22 C26 = C2012X7R1E474K: CAP, CERM, 0.47 µF, 25 V, +/- 10%, X7R, 0805; Manufacturer: TDK; Polarized: N; CompType: Capacitor; Value: 0.47uF; U/M: EA; Cap_F: 0.00000047; Tolerance_%: 10; ESR_ohm: 0.0101; Value1: 0.0101 ohm; VDC_V: 25; Value2: 25V; TaMin_C: -55; TaMax_C: 125; Cap_Case: 0805
C7 C10 C23 C25 = C2012X7R1E105K: CAP, CERM, 1 µF, 25 V, +/- 10%, X7R, 0805; Manufacturer: TDK; Polarized: N; CompType: Capacitor; Value: 1uF; U/M: EA; Cap_F: 0.000001; Tolerance_%: 10; ESR_ohm: 0.0075; Value1: 0.0075 ohm; VDC_V: 25; Value2: 25V; TaMin_C: -55; TaMax_C: 125; Cap_Case: 0805
C8 C24 = RT203C227MAJ10: CAP, CERM, 220 µF, 25 V, +/- 20%, X7R, 1075x300mil; Manufacturer: AVX; Tolerance_%: 20; VDC_V: 25; Value: 220uF; Polarized: N; CompType: Capacitor; U/M: EA; Cap_F: 0.00022; Value1: Unknown; Value2: 25V; TaMin_C: -55; TaMax_C: 125; Cap_Case: 27.3x7.62mm
C9 = 08055A221JAT2A: CAP, CERM, 220 pF, 50 V, +/- 5%, C0G/NP0, 0805; Manufacturer: AVX; Polarized: N; CompType: Capacitor; Value: 220pF; U/M: EA; Cap_F: 0.00000000022; Tolerance_%: 5; ESR_ohm: 0.23; Value1: 0.23 ohm; VDC_V: 50; Value2: 50V; TaMin_C: -55; TaMax_C: 125; Cap_Case: 0805
C13 C18 = C0805C223K5RACTU: CAP, CERM, 0.022 µF, 50 V, +/- 10%, X7R, 0805; Manufacturer: Kemet; Polarized: N; CompType: Capacitor; Value: 0.022uF; U/M: EA; Cap_F: 0.000000022; Tolerance_%: 10; ESR_ohm: 0.125; Value1: 0.125 ohm; VDC_V: 50; Value2: 50V; IRMS_A: 0.645; TaMin_C: -55; TaMax_C: 125; Cap_Case: 0805
C15 C28 = CGA5L2X7R2A684K160AA: CAP, CERM, 0.68 µF, 100 V, +/- 10%, X7R, 1206_190; Manufacturer: TDK; Polarized: N; CompType: Capacitor; Value: 0.68uF; U/M: EA; Cap_F: 0.00000068; Tolerance_%: 10; Value1: Unknown; VDC_V: 100; Value2: 100V; TaMin_C: -55; TaMax_C: 125; Cap_Case: 1206
C16 C32 = C3216X7R2A334K130AA: CAP, CERM, 0.33 µF, 100 V, +/- 10%, X7R, 1206; Manufacturer: TDK; Polarized: N; CompType: Capacitor; Value: 0.33uF; U/M: EA; Cap_F: 0.00000033; Tolerance_%: 10; Value1: Unknown; VDC_V: 100; Value2: 100V; TaMin_C: -55; TaMax_C: 125
C29 = 08055C103JAT2A: CAP, CERM, 0.01 µF, 50 V, +/- 5%, X7R, 0805; Manufacturer: AVX; Polarized: N; CompType: Capacitor; Value: 0.01uF; U/M: EA; Cap_F: 0.00000001; Tolerance_%: 5; ESR_ohm: 0.078; Value1: 0.078 ohm; VDC_V: 50; Value2: 50V; TaMin_C: -55; TaMax_C: 125; Cap_Case: 0805
C30 C31 C36 = GRM31CR71E106KA12L: CAP, CERM, 10 µF, 25 V, +/- 10%, X7R, 1206; Manufacturer: MuRata; Polarized: N; CompType: Capacitor; Value: 10uF; U/M: EA; Cap_F: 0.00001; Tolerance_%: 10; Value1: Unknown; VDC_V: 25; Value2: 25V; TaMin_C: -55; TaMax_C: 125; Cap_Case: 2220
C35 = EMK212BB7106MG-T: CAP, CERM, 10 µF, 16 V, +/- 20%, X7R, 0805; Manufacturer: Taiyo Yuden; Polarized: N; CompType: Capacitor; Value: 10uF; U/M: EA; Cap_F: 0.00001; Tolerance_%: 20; Value1: Unknown; VDC_V: 16; Value2: 16V; TaMin_C: -55; TaMax_C: 125; Cap_Case: 0805
C37 C38 = 08055A330JAT2A: CAP, CERM, 33 pF, 50 V, +/- 5%, C0G/NP0, 0805; Manufacturer: AVX; Polarized: N; CompType: Capacitor; Value: 33pF; U/M: EA; Cap_F: 0.000000000033; Tolerance_%: 5; ESR_ohm: 0.708; Value1: 0.708 ohm; VDC_V: 50; Value2: 50V; TaMin_C: -55; TaMax_C: 125; Cap_Case: 0805
C41 = 08055A101JAT2A: CAP, CERM, 100 pF, 50 V, +/- 5%, C0G/NP0, 0805; Manufacturer: AVX; Polarized: N; CompType: Capacitor; Value: 100pF; U/M: EA; Cap_F: 0.0000000001; Tolerance_%: 5; ESR_ohm: 0.356; Value1: 0.356 ohm; VDC_V: 50; Value2: 50V; TaMin_C: -55; TaMax_C: 125; Cap_Case: 0805
C42 = EGPA800ELL681MM30S: CAP, AL, 680 µF, 80 V, +/- 20%, 0.041 ohm, TH; Manufacturer: Chemi-Con; Polarized: Y; CompType: Capacitor; Value: 680uF; U/M: EA; Cap_F: 0.00068; Tolerance_%: 20; VDC_V: 80; Value2: 80V; ESR_ohm: 0.041; IRMS_A: 2.58; TaMin_C: -40; TaMax_C: 125; Cap_Case: 18x30mm
D1-D3 = 1N4148W-7-F: Diode, Ultrafast, 100 V, 0.15 A, SOD-123; Manufacturer: Diodes Inc.; U/M: EA; Vf_V: 1.25; Value: 100V; Value1: 0.15A; Value2: 1.25V; Io_A: 0.15; Vr_V: 100; TJmax_C: 150
F1 F3 = SSQ 12: FUSE BOARD MNT 12A 125VAC 86VDC; Manufacturer: Bel Fuse Inc; U/M: EA; Response Time: Fast; Fuse Type: Board Mount (Cartridge Style Excluded); Voltage Rating - DC: 86V; Approvals: CE, cULus; DC Cold Resistance: 0.005 Ohm; Voltage Rating - AC: 125V; Melting I²t: 70; Breaking Capacity @ Rated Voltage: 50A AC, 10kA DC
F2 F4 = 0456030.ER: FUSE BOARD MNT 30A 125VAC 72VDC; Manufacturer: Littelfuse Inc; U/M: EA; Fuse Type: Board Mount (Cartridge Style Excluded); DC Cold Resistance: 0.00132 Ohm; Breaking Capacity @ Rated Voltage: 100A AC, 500A DC; Response Time: Fast; Approvals: cULus, PSE; Voltage Rating - DC: 72V; Melting I²t: 81; Voltage Rating - AC: 125V
J1 = PJ-102A: CONN JACK POWER 2.1MM PCB; Manufacturer: CUI Inc; SymbolCreator: a0799628; CompType: Power Jack; U/M: EA; Current Rating: 2.5A; Plug/Mating Plug Diameter: 2.1mm ID, 5.5mm OD; Gender: Male; Number of Positions/Contacts: 2 Conductors, 3 Contacts; Shielding: Unshielded; Internal Switch(s): Single Switch, Normally Closed; VDC_V: 16VDC
J2 = 22-27-2031: CONN HEADER 3POS .100 VERT TIN; Manufacturer: Molex; SymbolCreator: a0799628; U/M: EA
J3 = TMDX28069USB_HALF ONE: DEV STICK USB PICCOLO F28069 HALF PART; PartNumber: SSW-108-01-T-D; Board Type: Evaluation Platform; Contents: Board(s)
J4 = TMDX28069USB_HALF TWO: DEV STICK USB PICCOLO F28069 HALF PART; PartNumber: SSW-108-01-T-D; Board Type: Evaluation Platform; Contents: Board(s)
L1 L2 = SER2918H-682KL: Inductor, Shielded E Core, Ferrite, 6.8uH, 28A, 0.0026 ohm, SMD; Manufacturer: Coilcraft; Ind_H: 6.8E-6; Imax_A: 28; Irms: 28A @ 40C rise; Isat: 45.9A @ 30% inductance drop; DCR_ohm: 0.0026; U/M: EA
PCBA1 = TMDX28069USB: Manufacturer: Texas Instruments; SymbolCreator: a0412235; CompType: PCBA
Q1-Q3 Q6-Q10 Q13-Q15 Q17-Q21 = BSC123N08NS3 G: MOSFET, N-CH, 80V, 55A, PG-TDSON-8; Manufacturer: Infineon Technologies; Alternate Manufacturer: None; U/M: EA; ChType: N; VdsMax_V: 80; Value1: 101 ohm; Rdson45_Ohm: 101; Value2: 19 nC; QgTyp_nC: 19; Vgs_V: 20; IdsMax_A: 55
Q4 Q11 = NX3020NAKW,115: MOSFET, N-CH, 30 V, 0.18 A, SOT-323; Manufacturer: NXP Semiconductor; Alternate Manufacturer: None; U/M: EA; ChType: N; Value: 30V; VdsMax_V: 30; Value1: 5.2 ohm; Rdson45_ohm: 5.2; Value2: 0.34 nC; QgTyp_nC: 0.34; Vgs_V: 20; IdsMax_A: 0.18
Q5 Q12 Q16 Q22 = FJV1845FMTF, Fairchild Semiconductor: Transistor, NPN, 120 V, 0.05 A, SOT-23; CompType: BJT; PNP: 0; NPN: 1; Vceo_V: 120; Vcesat1_V: 0.07; Value: 120 V; IcRated_A: 0.05; Value1: 0.05 A; HfeMax: 1200; TaMin_C: -55; TaMax_C: 150; U/M: EA
R1 R36 = LVK24R012FER: RES, 0.012, 1%, 1 W, 2412; Manufacturer: Ohmite; CompType: Resistor; Value: 0.012; Value_Code: R012; Tolerance_%: 1; Value2: 1W; TempCo: 50 ppm/C; EIA_Code: E96; U/M: EA
R2 = CRCW080539K2FKEA: RES, 39.2 k, 1%, 0.125 W, 0805; Manufacturer: Vishay-Dale; CompType: Resistor; Value: 39.2k; Res_ohm: 39200; Value_Code: 39k2; Tolerance_%: 1; Power_W: 0.125; Value2: 0.125W; VDC_V: 150; TempCo: 100 ppm/C; EIA_Code: E96; U/M: EA
R3 R17 = CRCW08052K00FKEA: RES, 2.00 k, 1%, 0.125 W, 0805; Manufacturer: Vishay-Dale; CompType: Resistor; Value: 2.00k; Res_ohm: 2000; Value_Code: 2k00; Tolerance_%: 1; Power_W: 0.125; Value2: 0.125W; VDC_V: 150; TempCo: 100 ppm/C; EIA_Code: E96; U/M: EA
R4-R6 R21-R25 R37 R38 R41 R47-R49 R51 = CRCW08053R01FKEA: RES, 3.01, 1%, 0.125 W, 0805; Manufacturer: Vishay-Dale; CompType: Resistor; Value: 3.01; Value_Code: 3R01; Tolerance_%: 1; Power_W: 0.125; Value2: 0.125W; VDC_V: 150; TempCo: 100 ppm/C; EIA_Code: E96; U/M: EA
R7 R8 R39 R40 R63-R66 = CRCW0805105RFKEA: RES, 105, 1%, 0.125 W, 0805; Manufacturer: Vishay-Dale; CompType: Resistor; Value_Code: 105R; Tolerance_%: 1; Power_W: 0.125; Value2: 0.125W; VDC_V: 150; TempCo: 100 ppm/C; EIA_Code: E96; U/M: EA; Value: 105
R9 R10 R18 R19 = CRCW080510K0FKEA: RES, 10.0 k, 1%, 0.125 W, 0805; Manufacturer: Vishay-Dale; CompType: Resistor; Value: 10.0k; Res_ohm: 10000; Value_Code: 10k0; Tolerance_%: 1; Power_W: 0.125; Value2: 0.125W; VDC_V: 150; TempCo: 100 ppm/C; EIA_Code: E96; U/M: EA
R11 R33 R42 R61 = CRCW08059K76FKEA: RES, 9.76 k, 1%, 0.125 W, 0805; Manufacturer: Vishay-Dale; CompType: Resistor; Value: 9.76k; Res_ohm: 9760; Value_Code: 9k76; Tolerance_%: 1; Power_W: 0.125; Value2: 0.125W; VDC_V: 150; TempCo: 100 ppm/C; EIA_Code: E96; U/M: EA
R12 R15 R20 R26 R30 R43 R45 R46 R52 = CRCW08051R00FKEA: RES, 1.00, 1%, 0.125 W, 0805; Manufacturer: Vishay-Dale; CompType: Resistor; Value: 1.00; Res_ohm: 1; Value_Code: 1R00; Power_W: 0.125; Value2: 0.125W; VDC_V: 150; TempCo: 100 ppm/C; EIA_Code: E96; U/M: EA
R13 R44 = WSL27262L000FEB: RES, 0.002, 1%, 3 W, 6.6x3x6.9mm; Manufacturer: Vishay Dale; CompType: Resistor; Value: 0.002; Res_ohm: 0.001; Value_Code: 1L000; Power_W: 3W; TempCo: ±75ppm/°C; EIA_Code: E96; U/M: EA
R14 = CRCW08058K25FKEA: RES, 8.25 k, 1%, 0.125 W, 0805; Manufacturer: Vishay-Dale; CompType: Resistor; Value: 8.25k; Res_ohm: 8250; Value_Code: 8k25; Tolerance_%: 1; Power_W: 0.125; Value2: 0.125W; VDC_V: 150; TempCo: 100 ppm/C; EIA_Code: E96; U/M: EA
R16 = CRCW1206499RFKEA: RES, 499, 1%, 0.25 W, 1206; Manufacturer: Vishay-Dale; CompType: Resistor; Value: 499; Value_Code: 499R; Tolerance_%: 1; Power_W: 0.25; Value2: 0.25W; VDC_V: 200; TempCo: 100 ppm/C; EIA_Code: E96; U/M: EA
R27 R31 R34 R35 = CRCW08054K99FKEA: RES, 4.99 k, 1%, 0.125 W, 0805; Manufacturer: Vishay-Dale; CompType: Resistor; Value: 4.99k; Res_ohm: 4990; Value_Code: 4k99; Tolerance_%: 1; Power_W: 0.125; Value2: 0.125W; VDC_V: 150; TempCo: 100 ppm/C; EIA_Code: E96; U/M: EA
R28 R29 R54 R55 = CRCW0805196RFKEA: RES, 196, 1%, 0.125 W, 0805; Manufacturer: Vishay-Dale; CompType: Resistor; Value_Code: 196R; Tolerance_%: 1; Power_W: 0.125; Value2: 0.125W; VDC_V: 150; TempCo: 100 ppm/C; EIA_Code: E96; U/M: EA; Value: 196
R32 R57 = CRCW0805392RFKEA: RES, 392, 1%, 0.125 W, 0805; Manufacturer: Vishay-Dale; CompType: Resistor; Value_Code: 392R; Tolerance_%: 1; Power_W: 0.125; Value2: 0.125W; VDC_V: 150; TempCo: 100 ppm/C; EIA_Code: E96; U/M: EA; Value: 392
R50 = CRCW08053R00JNEA: RES, 3.0, 5%, 0.125 W, 0805; Manufacturer: Vishay-Dale; CompType: Resistor; Value: 3.0; Res_ohm: 3; Value_Code: 3R00; Tolerance_%: 5; Power_W: 0.125; Value2: 0.125W; VDC_V: 150; TempCo: 200 ppm/C; EIA_Code: E24; U/M: EA
R58 = CRCW0805100KFKEA: RES, 100 k, 1%, 0.125 W, 0805; Manufacturer: Vishay-Dale; CompType: Resistor; Value: 100k; Res_ohm: 100000; Tolerance_%: 1; Power_W: 0.125; Value2: 0.125W; VDC_V: 150; TempCo: 100 ppm/C; EIA_Code: E96; U/M: EA
R59 = CRCW08051K00FKEA: RES, 1.00 k, 1%, 0.125 W, 0805; Manufacturer: Vishay-Dale; CompType: Resistor; Value: 1.00k; Res_ohm: 1000; Value_Code: 1k00; Tolerance_%: 1; Power_W: 0.125; Value2: 0.125W; VDC_V: 150; TempCo: 100 ppm/C; EIA_Code: E96; U/M: EA
T1 T2 = CB35-36-CY: Terminal 50A Lug; Manufacturer: Panduit; SymbolCreator: crossc; CompType: Screw Terminal; U/M: EA
T3 T4 = CB70-14-CY: Terminal 90A Lug; Manufacturer: Panduit; SymbolCreator: crossc; CompType: Screw Terminal; U/M: EA
TP1-TP56 = 5015: Test Point, Miniature, SMT; Manufacturer: Keystone; CompType: Test Point Loop; U/M: EA
U1 U4 = SM72295MA: IC, Photovoltaic Full Bridge Driver; Manufacturer: TI; Alternate Manufacturer: None; Area: 222.95 mm
U2 = TMP103AYFF: Low-Power, Digital Temperature Sensor with Two-Wire Interface in WCSP, YFF0004AAAA; Manufacturer: Texas Instruments; SymbolCreator: a0411947; CompType: IC; U/M: EA
U3 = TMP103BYFF: Low-Power, Digital Temperature Sensor with Two-Wire Interface in WCSP, YFF0004AAAA; Manufacturer: Texas Instruments; SymbolCreator: a0411947; CompType: IC; U/M: EA
U5 = LP2985-10DBVT: Single Output Low Noise LDO, 150 mA, Fixed 10 V Output, 2.2 to 16 V Input, with Low IQ, 5-pin SOT-23 (DBV), -40 to 125 degC, Green (RoHS & no Sb/Br); Manufacturer: Texas Instruments; Alternate Manufacturer: None; Alternate PartNumber: Equivalent; Accuracy(%): 1.5; Iout(Max)(A): 0.15; Iq(Typ)(mA): 0.85; SubFamily: Single Channel LDO; Vdo(Typ)(mV): 280; Vin(Max)(V): 16; Vin(Min)(V): 2.2; Vout Adj(Max)(V): 10
U6 = TPS7A4533DCQT: Single Output Fast Transient Response LDO, 1.5 A, Fixed 3.3 V Output, 2.1 to 20 V Input, 6-pin SOT-223 (DCQ), -40 to 125 degC, Green (RoHS & no Sb/Br); Manufacturer: Texas Instruments; Alternate Manufacturer: None; Alternate PartNumber: Equivalent; Accuracy(%): 1; Iout(Max)(A): 1.5; SubFamily: Single Channel LDO; Vdo(Typ)(mV): 300; Vin(Max)(V): 20; Vin(Min)(V): 2.1; Vout Adj(Max)(V): 3.3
